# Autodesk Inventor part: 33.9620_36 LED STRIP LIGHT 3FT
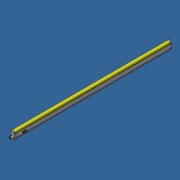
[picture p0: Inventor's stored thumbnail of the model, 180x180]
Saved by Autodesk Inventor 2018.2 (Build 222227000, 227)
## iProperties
Created: 2017-10
Part Number: 33.9620_36 LED STRIP LIGHT 3FT
Material: Generic
Document SubType Name: Modeling
Designer: Admin
Density: 1 g/cm^3
Appearance: Snow
Description: 36 LED STRIP LIGHT 3FT
Vendor: V
Author: Admin
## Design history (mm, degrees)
sketch "Sketch1"
  geometry: L1 (11, 0)-(-11, 0); L2 (-11, 0)-(-11, -25.332); L3 (-11, -25.332)-(11, -25.332); L4 (11, -25.332)-(11, 0); L5 (-11.5, -20.332)-(11.5, -20.332); L6 (11.5, -20.332)-(11.5, -25.332); L7 (11.5, -25.332)-(-11.5, -25.332); L8 (-11.5, -25.332)-(-11.5, -20.332); C1 r 10.668 at (0, 0); 4 further points
  constraints: 16 end point, 4 coincident, 4 parallel, 3 midpoint, 2 horizontal, 2 perpendicular, 1 centre point
  dimensions: "d0" = 21.336 diameter of C1; "d1" = 22 distance of L2.end L3.end; "d2" = 36 dimension on C1 L3; "d5" = 0 distance between parallel lines of L3 L7; "d6" = 23 distance of L5.start L5.end; "d7" = 5 distance between parallel lines of L3 L5
extrude "Extrusion1" new body sketch "Sketch1" stored distance "d3" = 825.0174; taper "d4" = 0 deg
sketch "Sketch2"
  geometry: L1 (-11, 0)-(-10.668, 0) reference; L2 (-11, -20.332)-(-11, 0) reference; L3 (11.5, -25.332)-(-11.5, -25.332) reference; L4 (11, 0)-(11, -20.332) reference; L5 (10.668, 0)-(11, 0) reference; L6 (-11.5, -25.332)-(-11.5, -20.332) reference; L7 (11.5, -20.332)-(11.5, -25.332) reference; L8 (11, -20.332)-(11.5, -20.332) reference; L9 (-11, 0)-(-10.668, 0) reference; L10 (-11, -20.332)-(-11, 0) reference; L11 (-11.5, -20.332)-(-11, -20.332) reference; L12 (-11.5, -25.332)-(-11.5, -20.332) reference; L13 (11.5, -25.332)-(-11.5, -25.332) reference; L14 (11.5, -20.332)-(11.5, -25.332) reference; L15 (11, -20.332)-(11.5, -20.332) reference; L16 (11, 0)-(11, -20.332) reference; L17 (10.668, 0)-(11, 0) reference; A1 r 10.668 centre (0, 0) between (10.668, 0) and (-10.668, 0) reference; A2 r 11 centre (0, 0) between (11, 0) and (-11, 0); A3 r 10.668 centre (0, 0) between (10.668, 0) and (-10.668, 0) reference
  constraints: 2 end point, 2 point on circle, 1 centre point, 1 coincident, 1 tangent
extrude "Extrusion2" join sketch "Sketch2" distance "d8" = 5; taper "d9" = 0 deg
mirror "Mirror1"
sketch "Sketch3"
  geometry: L1 (-2.2, -12.732)-(2.2, -12.732); L2 (2.2, -21.932)-(-2.2, -21.932); L3 (2.2, -13.932)-(-2.2, -13.932); L4 (-2.2, -20.732)-(2.2, -20.732); L5 (-11.5, -25.332)-(11.5, -25.332) reference; A1 r 4.6 centre (-2.2, -17.332) between (-2.2, -12.732) and (-2.2, -21.932); A2 r 4.6 centre (2.2, -17.332) between (2.2, -21.932) and (2.2, -12.732); A3 r 3.4 centre (-2.2, -17.332) between (-2.2, -13.932) and (-2.2, -20.732); A4 r 3.4 centre (2.2, -17.332) between (2.2, -20.732) and (2.2, -13.932); 2 further points
  constraints: 8 end point, 8 point on circle, 4 centre point, 2 midpoint, 2 parallel, 2 tangent, 1 equal radius, 1 horizontal, 1 horizontal alignment, 1 vertical alignment, 3 other
  dimensions: "d11" = 9.2 distance between parallel lines of L2 L1; "d12" = 13.6 dimension on A2 A1; "d13" = 1.2 distance between parallel lines of L3 L1; "d22" = 8 distance from line of A2.centre L5
extrude "Extrusion3" join sketch "Sketch3" distance "d14" = 10.8; taper "d15" = 0 deg
sketch "Sketch4"
  geometry: C1 r 0.75 at (-2.2, -17.332); C2 r 0.75 at (2.2, -17.332); A1 r 3.4 centre (2.2, -17.332) between (2.2, -20.732) and (2.2, -13.932) reference; A2 r 3.4 centre (-2.2, -17.332) between (-2.2, -13.932) and (-2.2, -20.732) reference; 1 further point
  constraints: 2 centre point, 2 coincident, 1 equal radius
  dimensions: "d16" = 1.5 diameter of C2
extrude "Extrusion4" join sketch "Sketch4" distance "d17" = 9.4; taper "d18" = 0 deg
fillet "Fillet1" dims "d19" = 0.75
sketch "Sketch5"
  geometry: L1 (-2.2, -20.732)-(2.2, -20.732) reference; L2 (2.2, -13.932)-(-2.2, -13.932) reference; L3 (2.2, -21.932)-(-2.2, -21.932) reference; L4 (-2.2, -12.732)-(2.2, -12.732) reference; C1 r 0.75 at (2.2, -17.332) reference; C2 r 0.75 at (-2.2, -17.332) reference; A1 r 3.4 centre (-2.2, -17.332) between (-2.2, -13.932) and (-2.2, -20.732) reference; A2 r 3.4 centre (2.2, -17.332) between (2.2, -20.732) and (2.2, -13.932) reference; A3 r 4.6 centre (2.2, -17.332) between (2.2, -21.932) and (2.2, -12.732) reference; A4 r 4.6 centre (-2.2, -17.332) between (-2.2, -12.732) and (-2.2, -21.932) reference
extrude "Extrusion5" cut sketch "Sketch5" distance "d20" = 10.8; taper "d21" = 0 deg
sketch "Sketch6"
  geometry: L1 (835.017, 0)-(0, 0) reference; L2 (0, 0)-(0, 20.332) reference; L3 (44, 10)-(65, 10); L4 (65, 10)-(65, 0.5); L5 (65, 0.5)-(44, 0.5); L6 (44, 0.5)-(44, 10); L7 (49.75, 8)-(59.25, 8); L8 (59.25, 2.5)-(49.75, 2.5); A1 r 2.75 centre (49.75, 5.25) between (49.75, 8) and (49.75, 2.5); A2 r 2.75 centre (59.25, 5.25) between (59.25, 2.5) and (59.25, 8); 4 further points
  constraints: 12 end point, 4 point on circle, 3 midpoint, 3 parallel, 2 centre point, 2 horizontal, 2 horizontal alignment, 2 tangent, 1 equal radius, 1 perpendicular, 1 vertical alignment
  dimensions: "d23" = 9.5 distance of L5.end L3.start; "d24" = 0.5 distance between parallel lines of L5 L1; "d25" = 21 distance of L3.start L3.end; "d26" = 44 distance between parallel lines of L6 L2; "d27" = 5.5 distance between parallel lines of L8 L7; "d28" = 15 dimension on A2 A1
extrude "Extrusion6" join sketch "Sketch6" distance "d29" = 1.55; taper "d30" = 0 deg
workplane "Work Plane1"
sketch "Sketch7"
  geometry: L1 (0, -5.75)-(0, 15.25) reference; L2 (0, -2.25)-(3.5, -2.25); L3 (3.5, -2.25)-(3.5, 11.75); L4 (3.5, 11.75)-(0, 11.75); L5 (0, 11.75)-(0, -2.25); L6 (1.55, 0)-(1.55, -2.75) reference; L7 (1.55, 12.25)-(1.55, 9.5) reference; A1 r 12.964 centre (14.411, 4.75) between (3.5, 11.75) and (3.5, -2.25); 1 further point
  constraints: 8 end point, 2 parallel, 2 point on circle, 1 centre point, 1 horizontal, 1 perpendicular, 1 point on line
  dimensions: "d31" = 0.5 distance from line of L6.end L2; "d32" = 0.5 distance from line of L4 L7.start; "d33" = 3.5 distance between parallel lines of L3 L1
extrude "Extrusion7" join sketch "Sketch7" stored distance "d34" = 4; taper "d35" = 0 deg
fillet "Fillet2" dims "d36" = 0.75
body "Solid1"
node "Projected Loop1"
node "Projected Loop2"
node "Projected Loop3"
node "Projected Loop4"
